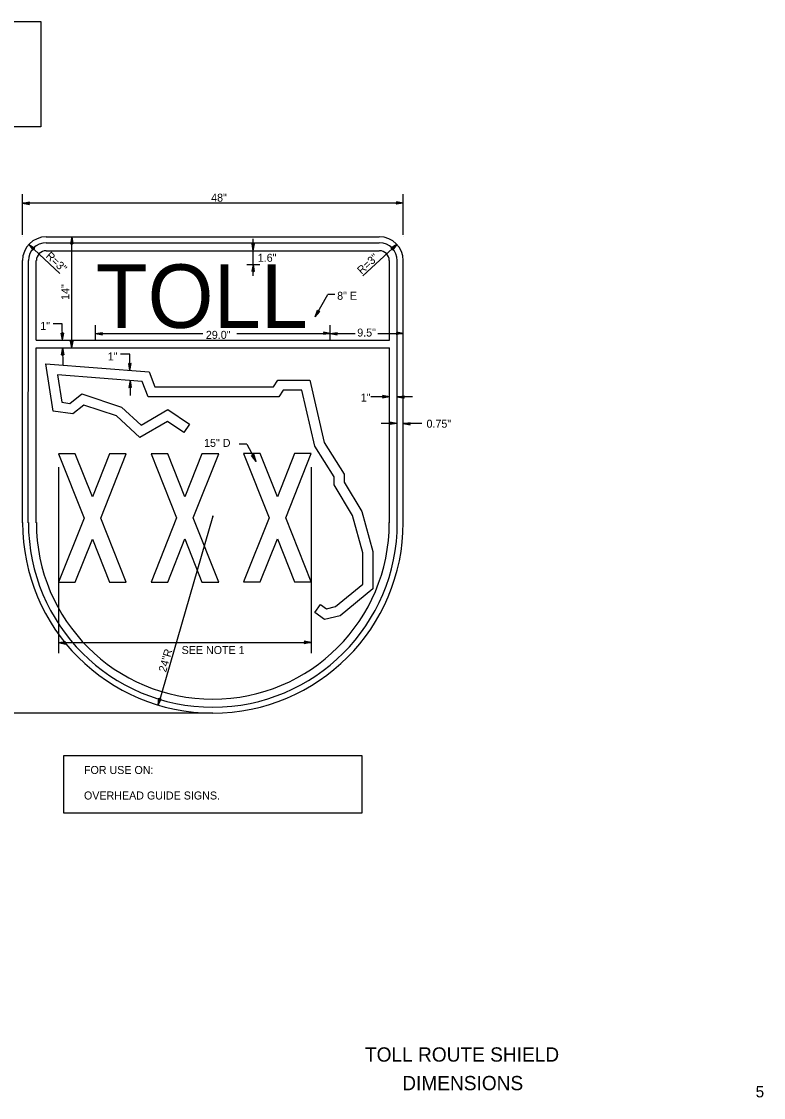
# Model space of a CAD drawing. Extents: x 52194 to 54069, y 8993 to 10153.
# Drawn here: x 53290 to 54069, y 9023 to 10153 of the extents above; entities that cross this region are included whole.
import ezdxf

# ---------------------------------------------------------------- set-up
doc = ezdxf.new("R2010")
doc.units = 0
for name, color, linetype in [('GSDims', 7, 'Continuous'), ('SignPanel', 7, 'Continuous'), ('TextAlert', 7, 'Continuous'), ('TextLabel', 7, 'Continuous'), ('TextMisc', 7, 'Continuous'), ('TextShtNo', 7, 'Continuous')]:
    doc.layers.add(name, color=color, linetype=linetype)

msp = doc.modelspace()

# ---------------------------------------------------------------- linework, layer by layer
at = {"layer": 'GSDims'}
for p, q in [((53290.6, 9929.1), (53290.6, 9971.7)), ((53290.6, 9962.4), (53297.9, 9963.6)), ((53290.6, 9962.4), (53297.6, 9962.9)), ((53297.4, 9962.3), (53297.9, 9963.6)), ((53690.6, 9962.4), (53683.4, 9963.8)), ((53683.4, 9963.8), (53683.9, 9962.5)), ((53690.6, 9962.4), (53683.6, 9963.2)), ((53690.6, 9929.1), (53690.6, 9971.7)), ((53290.6, 9962.4), (53297.9, 9961)), ((53290.6, 9962.4), (53297.6, 9961.7)), ((53690.6, 9962.4), (53290.6, 9962.4)), ((53297.9, 9961), (53297.4, 9962.3)), ((53683.9, 9962.5), (53683.3, 9961.3)), ((53690.6, 9962.4), (53683.3, 9961.3)), ((53690.6, 9962.4), (53683.6, 9961.9)), ((53290.6, 9927), (53290.6, 9927)), ((53297.4, 9919.1), (53303.5, 9915)), ((53297.4, 9919.1), (53301.7, 9913.1)), ((53297.4, 9919.1), (53302, 9913.8)), ((53297.4, 9919.1), (53302.9, 9914.7)), ((53297.4, 9919.1), (53329.9, 9888.5)), ((53342.3, 9927), (53340.9, 9919.8)), ((53340.9, 9919.8), (53342.2, 9920.3)), ((53342.3, 9927), (53341.5, 9920)), ((53342.2, 9920.3), (53343.4, 9919.7)), ((53342.3, 9927), (53343.4, 9919.7)), ((53342.3, 9927), (53342.8, 9920)), ((53342.3, 9810.3), (53342.3, 9927)), ((53533, 9912.4), (53531.8, 9919.7)), ((53533.1, 9919.2), (53531.8, 9919.7)), ((53533, 9912.4), (53532.5, 9919.4)), ((53533, 9912.4), (53533, 9925)), ((53533, 9912.4), (53534.4, 9919.7)), ((53533, 9912.4), (53533.7, 9919.4)), ((53534.4, 9919.7), (53533.1, 9919.2)), ((53683.9, 9918.9), (53648.2, 9886)), ((53683.9, 9918.9), (53677.6, 9915)), ((53683.9, 9918.9), (53678.3, 9914.7)), ((53683.9, 9918.9), (53679.1, 9913.8)), ((53683.9, 9918.9), (53679.3, 9913.1)), ((53690.6, 9927), (53690.6, 9927)), ((53301.7, 9913.1), (53302.2, 9914.4)), ((53302.2, 9914.4), (53303.5, 9915)), ((53533, 9898), (53533, 9912.4)), ((53677.6, 9915), (53678.9, 9914.4)), ((53678.9, 9914.4), (53679.3, 9913.1)), ((53526.4, 9898), (53540, 9898)), ((53533, 9898), (53531.6, 9890.8)), ((53533, 9898), (53532.2, 9891)), ((53533, 9886), (53533, 9898)), ((53533, 9898), (53534.1, 9890.7)), ((53533, 9898), (53533.5, 9891)), ((53531.6, 9890.8), (53532.9, 9891.3)), ((53532.9, 9891.3), (53534.1, 9890.7)), ((53598, 9843.1), (53611.4, 9866.3)), ((53618.6, 9866.3), (53611.4, 9866.3)), ((53598, 9843.1), (53600.7, 9850)), ((53601.5, 9848.9), (53600.7, 9850)), ((53598, 9843.1), (53601.1, 9849.4)), ((53598, 9843.1), (53602.2, 9848.8)), ((53598, 9843.1), (53602.9, 9848.7)), ((53602.9, 9848.7), (53601.5, 9848.9)), ((53332.4, 9835.7), (53322.7, 9835.7)), ((53332.6, 9818.7), (53332.4, 9835.7)), ((53367.3, 9818.6), (53367.3, 9834.2)), ((53614, 9818.6), (53614, 9834.2)), ((53332.6, 9818.7), (53331.3, 9826)), ((53332.6, 9825.5), (53331.3, 9826)), ((53332.6, 9818.7), (53332, 9825.7)), ((53332.6, 9818.7), (53333.9, 9826)), ((53333.9, 9826), (53332.6, 9825.5)), ((53332.6, 9818.7), (53333.2, 9825.7)), ((53342.3, 9810.3), (53341.1, 9817.6)), ((53342.4, 9817.1), (53341.1, 9817.6)), ((53342.3, 9810.3), (53341.8, 9817.3)), ((53342.3, 9810.3), (53343.7, 9817.6)), ((53342.3, 9810.3), (53343, 9817.3)), ((53343.7, 9817.6), (53342.4, 9817.1)), ((53367.3, 9825.4), (53374.6, 9826.6)), ((53367.3, 9825.4), (53374.3, 9825.9)), ((53367.3, 9825.4), (53374.6, 9824)), ((53367.3, 9825.4), (53374.3, 9824.7)), ((53367.3, 9825.4), (53480.2, 9825.4)), ((53374.1, 9825.3), (53374.6, 9826.6)), ((53374.6, 9824), (53374.1, 9825.3)), ((53515.8, 9825.4), (53614, 9825.4)), ((53607.3, 9825.5), (53606.7, 9824.3)), ((53614, 9825.4), (53606.7, 9824.3)), ((53614, 9825.4), (53606.8, 9826.8)), ((53606.8, 9826.8), (53607.3, 9825.5)), ((53614, 9825.4), (53607, 9826.2)), ((53614, 9825.4), (53607, 9824.9)), ((53614, 9825.4), (53621.3, 9826.6)), ((53614, 9825.4), (53621, 9825.9)), ((53614, 9825.4), (53621.3, 9824)), ((53614, 9825.4), (53621, 9824.7)), ((53614, 9825.4), (53640.1, 9825.4)), ((53620.8, 9825.3), (53621.3, 9826.6)), ((53621.3, 9824), (53620.8, 9825.3)), ((53663.8, 9825.4), (53690.6, 9825.4)), ((53683.9, 9825.5), (53683.3, 9824.3)), ((53690.6, 9825.4), (53683.3, 9824.3)), ((53690.6, 9825.4), (53683.4, 9826.8)), ((53683.4, 9826.8), (53683.9, 9825.5)), ((53690.6, 9825.4), (53683.6, 9826.2)), ((53690.6, 9825.4), (53683.6, 9824.9)), ((53332.7, 9810.4), (53331.3, 9803.1)), ((53332.7, 9810.4), (53332, 9803.4)), ((53332.7, 9810.4), (53333.9, 9803.1)), ((53332.7, 9810.4), (53333.2, 9803.4)), ((53332.7, 9810.4), (53332.9, 9792.4)), ((53331.3, 9803.1), (53332.6, 9803.7)), ((53332.6, 9803.7), (53333.9, 9803.1)), ((53403.4, 9803.7), (53393.6, 9803.7)), ((53403.5, 9786.7), (53402.3, 9794)), ((53403.6, 9793.5), (53402.3, 9794)), ((53403.5, 9786.7), (53403, 9793.7)), ((53403.5, 9786.7), (53403.4, 9803.7)), ((53403.5, 9786.7), (53404.9, 9794)), ((53403.5, 9786.7), (53404.2, 9793.7)), ((53404.9, 9794), (53403.6, 9793.5)), ((53403.7, 9776.2), (53402.3, 9768.9)), ((53403.7, 9776.2), (53403, 9769.2)), ((53403.7, 9776.2), (53404.9, 9768.9)), ((53403.7, 9776.2), (53404.2, 9769.2)), ((53403.7, 9776.2), (53403.8, 9760.4)), ((53402.3, 9768.9), (53403.6, 9769.5)), ((53403.6, 9769.5), (53404.9, 9768.9)), ((53676.1, 9758.9), (53668.9, 9760.3)), ((53668.9, 9760.3), (53669.4, 9759)), ((53676.1, 9758.9), (53669.1, 9759.6)), ((53684.4, 9758.9), (53691.7, 9760)), ((53684.4, 9758.9), (53691.4, 9759.4)), ((53691.2, 9758.8), (53691.7, 9760)), ((53676.1, 9758.9), (53656.6, 9758.9)), ((53669.4, 9759), (53668.8, 9757.7)), ((53676.1, 9758.9), (53668.8, 9757.7)), ((53676.1, 9758.9), (53669.1, 9758.4)), ((53684.4, 9758.9), (53691.7, 9757.5)), ((53684.4, 9758.9), (53691.4, 9758.1)), ((53700.4, 9758.9), (53684.4, 9758.9)), ((53691.7, 9757.5), (53691.2, 9758.8)), ((53684, 9731.1), (53667.5, 9731.1)), ((53684, 9731.1), (53676.7, 9732.5)), ((53676.7, 9732.5), (53677.2, 9731.2)), ((53677.2, 9731.2), (53676.7, 9729.9)), ((53684, 9731.1), (53676.7, 9729.9)), ((53684, 9731.1), (53677, 9731.8)), ((53684, 9731.1), (53677, 9730.6)), ((53690.6, 9731.1), (53697.9, 9732.2)), ((53690.6, 9731.1), (53697.6, 9731.6)), ((53690.6, 9731.1), (53697.9, 9729.7)), ((53690.6, 9731.1), (53697.6, 9730.3)), ((53710.2, 9731.1), (53690.6, 9731.1)), ((53697.4, 9731), (53697.9, 9732.2)), ((53697.9, 9729.7), (53697.4, 9731)), ((53526.4, 9709.4), (53518.4, 9709.4)), ((53526.4, 9709.4), (53536, 9691.3)), ((53532.7, 9697.8), (53531.3, 9697.6)), ((53536, 9691.3), (53531.3, 9697.6)), ((53536, 9691.3), (53532.1, 9697.7)), ((53533.6, 9699), (53532.7, 9697.8)), ((53536, 9691.3), (53533.1, 9698.4)), ((53536, 9691.3), (53533.6, 9699)), ((53328.6, 9685.1), (53328.6, 9490)), ((53593.9, 9685.1), (53593.9, 9490)), ((53490.6, 9633.9), (53433.3, 9435.4)), ((53490.6, 9633.9), (53490.6, 9633.9)), ((53490.6, 9633.9), (53490.6, 9633.9)), ((53328.6, 9501.1), (53335.9, 9502.3)), ((53328.6, 9501.1), (53335.6, 9501.6)), ((53328.6, 9501.1), (53593.9, 9501.1)), ((53328.6, 9501.1), (53335.8, 9499.5)), ((53328.6, 9501.1), (53335.6, 9500.3)), ((53335.3, 9501), (53335.9, 9502.3)), ((53335.8, 9499.5), (53335.3, 9501)), ((53587.2, 9501.2), (53586.6, 9499.8)), ((53593.9, 9501.1), (53586.6, 9499.8)), ((53593.9, 9501.1), (53586.7, 9502.6)), ((53586.7, 9502.6), (53587.2, 9501.2)), ((53593.9, 9501.1), (53586.9, 9501.9)), ((53593.9, 9501.1), (53586.9, 9500.5)), ((53433.3, 9435.4), (53433.9, 9442.7)), ((53433.3, 9435.4), (53434.5, 9442.3)), ((53433.3, 9435.4), (53436.4, 9442.1)), ((53433.3, 9435.4), (53435.7, 9442)), ((53433.9, 9442.7), (53435.1, 9441.9)), ((53435.1, 9441.9), (53436.4, 9442.1)), ((53490.5, 9427), (53246, 9427)), ((53290.6, 9426.9), (53290.6, 9426.9))]:
    msp.add_line(p, q, dxfattribs=at)
for radius in [0.141, 0.141, 0.0707]:
    msp.add_circle((53490.6, 9633.9), radius, dxfattribs=at)
at = {"layer": 'SignPanel'}
for p, q in [((53315.6, 9927), (53665.5, 9927)), ((53315.6, 9920.7), (53665.5, 9920.7)), ((53315.6, 9912.4), (53665.5, 9912.4)), ((53290.5, 9626.9), (53290.6, 9902)), ((53296.7, 9626.9), (53296.8, 9902)), ((53305.1, 9818.6), (53305.1, 9902)), ((53676.1, 9818.6), (53676.1, 9902)), ((53684.4, 9626.9), (53684.4, 9902)), ((53690.6, 9626.9), (53690.6, 9902)), ((53305.1, 9818.6), (53357.3, 9818.6)), ((53357.3, 9818.6), (53676.1, 9818.6)), ((53305, 9626.9), (53305.1, 9810.3)), ((53305.1, 9810.3), (53676.1, 9810.3)), ((53676.1, 9626.9), (53676.1, 9810.3)), ((53315, 9793.6), (53423.6, 9785.2)), ((53322.7, 9743.9), (53315, 9793.6)), ((53416.2, 9775.2), (53327.4, 9782.1)), ((53327.4, 9782.1), (53331.8, 9753.3)), ((53423.6, 9785.2), (53429.7, 9769.6)), ((53422.5, 9759.1), (53416.2, 9775.2)), ((53554.3, 9769.6), (53559, 9776.5)), ((53559, 9776.5), (53592.5, 9776.5)), ((53592.5, 9776.5), (53607.7, 9711.2)), ((53340.4, 9752.2), (53352.8, 9762)), ((53352.8, 9762), (53394.7, 9748.3)), ((53429.7, 9769.6), (53554.3, 9769.6)), ((53564.6, 9766), (53559.9, 9759.1)), ((53584.2, 9766), (53564.6, 9766)), ((53597.9, 9707.1), (53584.2, 9766)), ((53331.8, 9753.3), (53340.4, 9752.2)), ((53354.9, 9750.3), (53343.5, 9741.3)), ((53389.3, 9739.1), (53354.9, 9750.3)), ((53394.7, 9748.3), (53415.3, 9729.3)), ((53559.9, 9759.1), (53422.5, 9759.1)), ((53343.5, 9741.3), (53322.7, 9743.9)), ((53413.9, 9716.3), (53389.3, 9739.1)), ((53415.3, 9729.3), (53443.2, 9745.6)), ((53443.2, 9745.6), (53465.9, 9730.3)), ((53442.8, 9733.3), (53413.9, 9716.3)), ((53460, 9721.6), (53442.8, 9733.3)), ((53465.9, 9730.3), (53460, 9721.6)), ((53617.9, 9675), (53597.9, 9707.1)), ((53607.7, 9711.2), (53628.4, 9678)), ((53346.1, 9699.2), (53328.6, 9699.2)), ((53328.6, 9699.2), (53355.3, 9631.8)), ((53364.1, 9653.9), (53346.1, 9699.2)), ((53382.1, 9699.2), (53364.1, 9653.9)), ((53372.9, 9631.8), (53399.7, 9699.2)), ((53399.7, 9699.2), (53382.1, 9699.2)), ((53443.3, 9699.3), (53425.7, 9699.3)), ((53425.7, 9699.3), (53452.5, 9631.9)), ((53461.3, 9654), (53443.3, 9699.3)), ((53479.2, 9699.3), (53461.3, 9654)), ((53470, 9631.9), (53496.8, 9699.3)), ((53496.8, 9699.3), (53479.2, 9699.3)), ((53540.4, 9699.4), (53522.8, 9699.4)), ((53522.8, 9699.4), (53549.6, 9632)), ((53558.4, 9654.1), (53540.4, 9699.4)), ((53576.4, 9699.4), (53558.4, 9654.1)), ((53567.2, 9632), (53593.9, 9699.4)), ((53593.9, 9699.4), (53576.4, 9699.4)), ((53617.9, 9666.7), (53617.9, 9675)), ((53628.4, 9678), (53628.4, 9669.6)), ((53628.4, 9669.6), (53647.1, 9638.8)), ((53637.4, 9634.6), (53617.9, 9666.7)), ((53647.1, 9638.8), (53658.6, 9596.7)), ((53355.3, 9631.8), (53328.6, 9564.4)), ((53399.7, 9564.4), (53372.9, 9631.8)), ((53452.5, 9631.9), (53425.7, 9564.6)), ((53496.8, 9564.6), (53470, 9631.9)), ((53549.6, 9632), (53522.8, 9564.7)), ((53593.9, 9564.7), (53567.2, 9632)), ((53648.1, 9595.3), (53637.4, 9634.6)), ((53346.1, 9564.4), (53364.1, 9609.7)), ((53364.1, 9609.7), (53382.1, 9564.4)), ((53443.3, 9564.6), (53461.3, 9609.8)), ((53461.3, 9609.8), (53479.2, 9564.6)), ((53540.4, 9564.7), (53558.4, 9610)), ((53558.4, 9610), (53576.4, 9564.7)), ((53648.1, 9562.3), (53648.1, 9595.3)), ((53658.6, 9596.7), (53658.6, 9557.4)), ((53328.6, 9564.4), (53346.1, 9564.4)), ((53382.1, 9564.4), (53399.7, 9564.4)), ((53425.7, 9564.6), (53443.3, 9564.6)), ((53479.2, 9564.6), (53496.8, 9564.6)), ((53522.8, 9564.7), (53540.4, 9564.7)), ((53576.4, 9564.7), (53593.9, 9564.7)), ((53619.5, 9538.9), (53648.1, 9562.3)), ((53658.6, 9557.4), (53624.3, 9529.2)), ((53597.6, 9532.5), (53603.6, 9541.1)), ((53603.6, 9541.1), (53610.1, 9536.6)), ((53610.1, 9536.6), (53619.5, 9538.9)), ((53608, 9525.3), (53597.6, 9532.5)), ((53624.3, 9529.2), (53608, 9525.3))]:
    msp.add_line(p, q, dxfattribs=at)
for centre, radius, start, end in [((53315.6, 9902), 25, 90, 179.9792), ((53315.6, 9902), 18.8, 90, 179.9792), ((53665.6, 9902), 25, 0, 90), ((53665.6, 9902), 18.8, 0, 90), ((53315.6, 9902), 10.4, 90, 179.9792), ((53665.6, 9902), 10.4, 0, 90), ((53490.6, 9627), 200, 180, 0), ((53490.6, 9627), 193.8, 180, 0), ((53490.6, 9627), 185.4, 180, 0)]:
    msp.add_arc(centre, radius, start, end, dxfattribs=at)
at = {"layer": 'TextAlert'}
msp.add_lwpolyline([(53057.8, 10153), (53309.9, 10153), (53309.9, 10042.3), (53057.8, 10042.3)], close=True, dxfattribs=at)
at = {"layer": 'TextLabel'}
msp.add_lwpolyline([(53334.1, 9382.6), (53647.1, 9382.6), (53647.1, 9321.8), (53334.1, 9321.8)], close=True, dxfattribs=at)

# ---------------------------------------------------------------- texts
at = {"layer": 'GSDims'}
for s, p in [('48"', (53488.8, 9963.9)), ('1.6"', (53537.8, 9900.8)), ('8" E ', (53621.2, 9860.9)), ('1"', (53309.3, 9829.3)), ('29.0"', (53483.3, 9819.9)), ('9.5"', (53642.3, 9822.3)), ('1"', (53380.2, 9797.3)), ('1"', (53646, 9754.1)), ('0.75"', (53715.1, 9726.6)), ('15" D', (53481.4, 9706.5)), ('SEE NOTE 1', (53457.8, 9489))]:
    msp.add_text(s, height=8.4, dxfattribs=at).set_placement(p)
for s, rotation, p in [('R=3"', 316.6507, (53314.4, 9906.1)), ('R=3"', 42.6037, (53646.9, 9887.2)), ('14"', 90, (53339.7, 9860.8)), ('.', 90, (53491.6, 9631.8)), ('24"R', 73.9233, (53441.4, 9469.3))]:
    msp.add_text(s, height=8.4, rotation=rotation, dxfattribs=at).set_placement(p)
at = {"layer": 'SignPanel'}
msp.add_text('TOLL', height=66.65, dxfattribs=at).set_placement((53367.6, 9831.4))
at = {"layer": 'TextLabel'}
for s, p in [('FOR USE ON:', (53355.2, 9363.1)), ('OVERHEAD GUIDE SIGNS.', (53355.2, 9336.3))]:
    msp.add_text(s, height=8.4, dxfattribs=at).set_placement(p)
at = {"layer": 'TextMisc'}
for s, p in [('   TOLL ROUTE SHIELD    ', (53633.7, 9061.1)), ('       DIMENSIONS       ', (53650.6, 9031.1))]:
    msp.add_text(s, height=15, rotation=360, dxfattribs=at).set_placement(p)
at = {"layer": 'TextShtNo'}
msp.add_text('5', height=12, rotation=360, dxfattribs=at).set_placement((54060.9, 9023.6))

doc.saveas('drawing.dxf')
